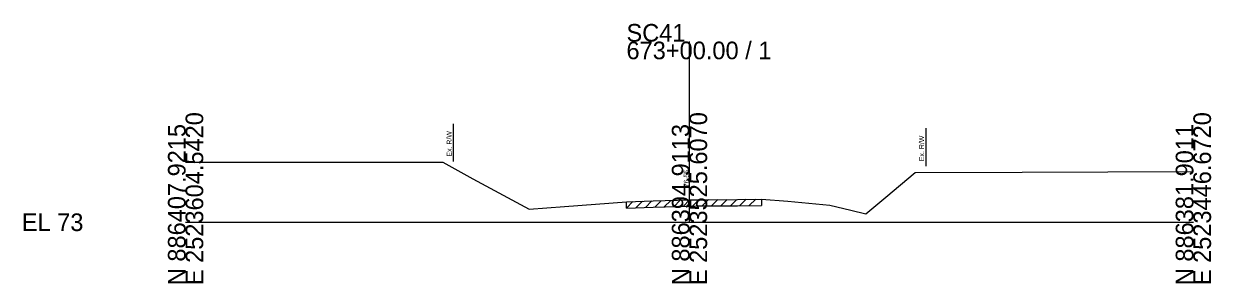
# Model space of a CAD drawing. Extents: x -26 to 183, y -10 to 24021.
# Drawn here: x -25.7 to 162.8, y 5490.3 to 5531.5 of the extents above; entities that cross this region are included whole.
import ezdxf

# ---------------------------------------------------------------- set-up
doc = ezdxf.new("R2010")
doc.units = 0
for name, color, linetype in [('RD_GPK_XS_Cell', 7, 'Continuous'), ('RD_XS_ExGround', 7, 'Continuous'), ('RD_XS_ExPaveRet', 7, 'Continuous'), ('RD_XS_ExRW', 7, 'Continuous'), ('RD_XS_TX_Elev_EX', 7, 'Continuous')]:
    doc.layers.add(name, color=color, linetype=linetype)

msp = doc.modelspace()

# ---------------------------------------------------------------- linework, layer by layer
at = {"layer": 'RD_GPK_XS_Cell'}
for p, q in [((80, 5500), (80, 5528.69)), ((0, 5500), (80, 5500)), ((80, 5500), (160, 5500))]:
    msp.add_line(p, q, dxfattribs=at)
at = {"layer": 'RD_XS_ExGround'}
for p, q in [((0, 5509.52), (21.07, 5509.55)), ((21.07, 5509.55), (40.85, 5509.56)), ((40.85, 5509.56), (45.63, 5506.91)), ((111.16, 5503.99), (115.82, 5507.91)), ((115.82, 5507.91), (132.8, 5507.95)), ((132.8, 5507.95), (160, 5508.06)), ((45.63, 5506.91), (54.53, 5502.08)), ((70, 5503.26), (74.25, 5503.38)), ((74.25, 5503.38), (80, 5503.55)), ((80, 5503.55), (81.38, 5503.58)), ((81.38, 5503.58), (87.61, 5503.63)), ((87.61, 5503.63), (91.43, 5503.67)), ((91.43, 5503.67), (95.62, 5503.32)), ((95.62, 5503.32), (102.27, 5502.72)), ((108.01, 5501.33), (111.16, 5503.99)), ((54.53, 5502.08), (60.14, 5502.51)), ((60.14, 5502.51), (70, 5503.26)), ((102.27, 5502.72), (105.62, 5501.91)), ((105.62, 5501.91), (108.01, 5501.33))]:
    msp.add_line(p, q, dxfattribs=at)
at = {"layer": 'RD_XS_ExPaveRet'}
for p, q in [((70, 5502.26), (71.03, 5503.29)), ((71.5, 5502.3), (72.53, 5503.33)), ((73, 5502.35), (74.03, 5503.38)), ((74.5, 5502.39), (75.53, 5503.42)), ((76, 5502.43), (77.03, 5503.46)), ((77.5, 5502.47), (78.53, 5503.5)), ((79, 5502.52), (80.03, 5503.55)), ((80.5, 5502.56), (81.52, 5503.59)), ((82, 5502.59), (83, 5503.6)), ((83.5, 5502.6), (84.5, 5503.61)), ((85, 5502.61), (86, 5503.62)), ((86.5, 5502.63), (87.5, 5503.63)), ((88, 5502.64), (89.01, 5503.65)), ((89.5, 5502.65), (90.51, 5503.66)), ((91.43, 5503.67), (91.43, 5502.67)), ((70, 5502.26), (70, 5503.26)), ((70, 5502.26), (74.25, 5502.38)), ((74.25, 5502.38), (80, 5502.55)), ((80, 5502.55), (81.38, 5502.58)), ((81.38, 5502.58), (87.61, 5502.63)), ((87.61, 5502.63), (91.43, 5502.67))]:
    msp.add_line(p, q, dxfattribs=at)
at = {"layer": 'RD_XS_ExRW'}
for p, q in [((42.5, 5515.65), (42.5, 5509.65)), ((117.5, 5514.92), (117.5, 5508.92))]:
    msp.add_line(p, q, dxfattribs=at)

# ---------------------------------------------------------------- texts
at = {"layer": 'RD_GPK_XS_Cell'}
for s, p in [('SC41', (70, 5528.69)), ('673+00.00 / 1', (70, 5525.89)), ('EL 73', (-26, 5498.6))]:
    msp.add_text(s, height=2.8, dxfattribs=at).set_placement(p)
for s, p in [('E 2523604.5420', (2.8, 5490)), ('E 2523525.6070', (82.8, 5490)), ('E 2523446.6720', (162.8, 5490)), ('N 886407.9215', (0, 5490)), ('N 886394.9113', (80, 5490)), ('N 886381.9011', (160, 5490))]:
    msp.add_text(s, height=2.8, rotation=90, dxfattribs=at).set_placement(p)
at = {"layer": 'RD_XS_ExRW'}
for p in [(42.25, 5510.43), (117.25, 5509.7)]:
    msp.add_text('Ex. R/W ', height=0.8, rotation=90, dxfattribs=at).set_placement(p)
at = {"layer": 'RD_XS_TX_Elev_EX'}
msp.add_text('76.55', height=0.8, rotation=90, dxfattribs=at).set_placement((79.9, 5505.55))

doc.saveas('drawing.dxf')
